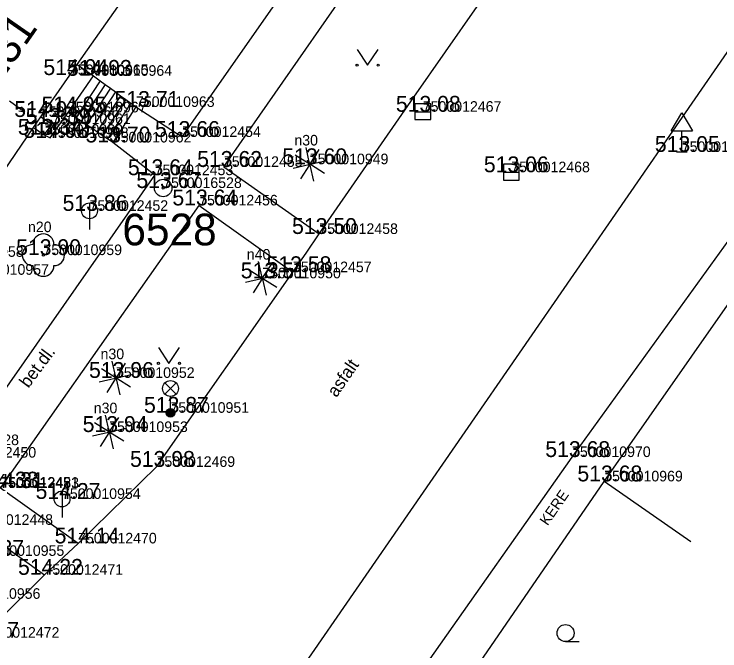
# Model space of a CAD drawing. Extents: x -669251 to -668549, y -1128351 to -1127698.
# Drawn here: x -668932.59 to -668899.21, y -1127946.27 to -1127916.15 of the extents above; entities that cross this region are included whole.
import ezdxf

# ---------------------------------------------------------------- set-up
doc = ezdxf.new("R2010")
doc.units = 0
for name, color, linetype in [('Vrstva 1', 7, 'Continuous'), ('Vrstva 10', 7, 'Continuous'), ('Vrstva 11', 7, 'Continuous'), ('Vrstva 2', 7, 'Continuous'), ('Vrstva 21', 7, 'Continuous'), ('Vrstva 22', 7, 'Continuous'), ('Vrstva 24', 7, 'Continuous'), ('Vrstva 27', 7, 'Continuous'), ('Vrstva 3', 7, 'Continuous'), ('Vrstva 33', 7, 'Continuous'), ('Vrstva 34', 7, 'Continuous'), ('Vrstva 36', 7, 'Continuous'), ('Vrstva 40', 7, 'Continuous'), ('Vrstva 43', 7, 'Continuous'), ('Vrstva 47', 7, 'Continuous'), ('Vrstva 5', 7, 'Continuous'), ('Vrstva 6', 7, 'Continuous'), ('Vrstva 63', 7, 'Continuous'), ('Vrstva 7', 7, 'Continuous')]:
    doc.layers.add(name, color=color, linetype=linetype)

msp = doc.modelspace()

# ---------------------------------------------------------------- linework, layer by layer
at = {"layer": 'Vrstva 1'}
for p, q in [((-668929.951, -1127919.033), (-668929.951, -1127919.033)), ((-668928.837, -1127919.068), (-668928.837, -1127919.068)), ((-668930.041, -1127920.798), (-668930.041, -1127920.798)), ((-668926.826, -1127920.54), (-668926.826, -1127920.54)), ((-668913.26, -1127920.768), (-668913.26, -1127920.768)), ((-668931.329, -1127921.015), (-668931.329, -1127921.015)), ((-668930.79, -1127921.349), (-668930.79, -1127921.349)), ((-668931.163, -1127921.858), (-668931.163, -1127921.858)), ((-668930.892, -1127922.005), (-668930.892, -1127922.005)), ((-668924.639, -1127921.96), (-668924.639, -1127921.96)), ((-668927.923, -1127922.22), (-668927.923, -1127922.22)), ((-668901.009, -1127922.669), (-668901.009, -1127922.669)), ((-668922.666, -1127923.376), (-668922.666, -1127923.376)), ((-668918.604, -1127923.25), (-668918.604, -1127923.25)), ((-668925.942, -1127923.768), (-668925.942, -1127923.768)), ((-668909.075, -1127923.63), (-668909.075, -1127923.63)), ((-668925.54, -1127924.375), (-668925.54, -1127924.375)), ((-668929.023, -1127925.456), (-668929.023, -1127925.456)), ((-668923.838, -1127925.199), (-668923.838, -1127925.199)), ((-668918.155, -1127926.549), (-668918.155, -1127926.549)), ((-668931.205, -1127927.548), (-668931.205, -1127927.548)), ((-668919.399, -1127928.356), (-668919.399, -1127928.356)), ((-668920.854, -1127928.647), (-668920.854, -1127928.647)), ((-668927.772, -1127933.358), (-668927.772, -1127933.358)), ((-668925.194, -1127935.007), (-668925.194, -1127935.007)), ((-668928.093, -1127935.917), (-668928.093, -1127935.917)), ((-668906.199, -1127937.1), (-668906.199, -1127937.1)), ((-668925.854, -1127937.566), (-668925.854, -1127937.566)), ((-668904.68, -1127938.252), (-668904.68, -1127938.252)), ((-668930.324, -1127939.081), (-668930.324, -1127939.081)), ((-668929.563, -1127941.186), (-668929.563, -1127941.186)), ((-668931.154, -1127942.671), (-668931.154, -1127942.671))]:
    msp.add_line(p, q, dxfattribs=at)
at = {"layer": 'Vrstva 10'}
for p, q in [((-668924.639, -1127921.96), (-668915.645, -1127909.032)), ((-668923.205, -1127953.195), (-668892.876, -1127909.291)), ((-668922.666, -1127923.376), (-668913.667, -1127910.439)), ((-668926.826, -1127920.54), (-668924.639, -1127921.96)), ((-668925.942, -1127923.768), (-668927.923, -1127922.22)), ((-668922.666, -1127923.376), (-668918.155, -1127926.549)), ((-668935.267, -1127937.128), (-668925.942, -1127923.768)), ((-668933.238, -1127938.566), (-668923.838, -1127925.199)), ((-668923.838, -1127925.199), (-668919.399, -1127928.356)), ((-668925.854, -1127937.566), (-668919.399, -1127928.356)), ((-668929.563, -1127941.186), (-668925.854, -1127937.566)), ((-668929.563, -1127941.186), (-668933.238, -1127938.566)), ((-668934.469, -1127940.308), (-668931.154, -1127942.671)), ((-668931.154, -1127942.671), (-668929.563, -1127941.186)), ((-668934.167, -1127945.646), (-668931.154, -1127942.671))]:
    msp.add_line(p, q, dxfattribs=at)
msp.add_lwpolyline([(-668919.399, -1127928.356), (-668918.777, -1127927.452), (-668918.155, -1127926.549), (-668913.684, -1127920.082), (-668909.196, -1127913.626), (-668908.554, -1127912.71), (-668907.91, -1127911.796), (-668905.751, -1127908.702), (-668903.61, -1127905.58), (-668903.236, -1127904.974), (-668902.699, -1127903.845), (-668902.381, -1127902.958), (-668902.019, -1127901.594), (-668901.763, -1127900.232), (-668901.68, -1127899.538), (-668901.657, -1127898.3), (-668901.741, -1127897.363), (-668901.861, -1127896.66), (-668902.133, -1127895.616), (-668902.513, -1127894.594), (-668903.003, -1127893.553), (-668903.409, -1127892.816), (-668904.098, -1127891.771)], dxfattribs=at)
at = {"layer": 'Vrstva 11'}
for p, q in [((-668929.604, -1127918.534), (-668928.837, -1127919.068)), ((-668930.041, -1127920.798), (-668928.837, -1127919.068)), ((-668928.837, -1127919.068), (-668928.523, -1127919.298)), ((-668928.523, -1127919.298), (-668929.667, -1127921.049)), ((-668928.281, -1127919.475), (-668929.417, -1127921.216)), ((-668928.523, -1127919.298), (-668928.281, -1127919.475)), ((-668928.281, -1127919.475), (-668928.038, -1127919.653)), ((-668928.038, -1127919.653), (-668929.168, -1127921.384)), ((-668927.796, -1127919.83), (-668928.919, -1127921.551)), ((-668928.038, -1127919.653), (-668927.796, -1127919.83)), ((-668927.796, -1127919.83), (-668927.553, -1127920.008)), ((-668927.553, -1127920.008), (-668928.67, -1127921.718)), ((-668927.553, -1127920.008), (-668927.311, -1127920.185)), ((-668927.311, -1127920.185), (-668928.421, -1127921.886)), ((-668927.068, -1127920.363), (-668928.172, -1127922.053)), ((-668927.311, -1127920.185), (-668927.068, -1127920.363)), ((-668927.068, -1127920.363), (-668926.826, -1127920.54)), ((-668930.892, -1127922.005), (-668930.041, -1127920.798)), ((-668929.667, -1127921.049), (-668930.041, -1127920.798)), ((-668926.826, -1127920.54), (-668927.923, -1127922.22)), ((-668929.417, -1127921.216), (-668929.667, -1127921.049)), ((-668931.669, -1127921.512), (-668931.163, -1127921.858)), ((-668929.168, -1127921.384), (-668929.417, -1127921.216)), ((-668928.919, -1127921.551), (-668929.168, -1127921.384)), ((-668928.67, -1127921.718), (-668928.919, -1127921.551)), ((-668928.421, -1127921.886), (-668928.67, -1127921.718)), ((-668931.163, -1127921.858), (-668930.892, -1127922.005)), ((-668928.172, -1127922.053), (-668928.421, -1127921.886)), ((-668927.923, -1127922.22), (-668928.172, -1127922.053))]:
    msp.add_line(p, q, dxfattribs=at)
at = {"layer": 'Vrstva 21'}
for p, q in [((-668906.199, -1127937.1), (-668895.924, -1127922.866)), ((-668915.923, -1127950.905), (-668906.199, -1127937.1))]:
    msp.add_line(p, q, dxfattribs=at)
at = {"layer": 'Vrstva 22'}
for p, q in [((-668918.612, -1127923.21), (-668918.784, -1127922.456)), ((-668918.638, -1127923.23), (-668919.294, -1127922.816)), ((-668918.17, -1127922.56), (-668918.584, -1127923.216)), ((-668918.564, -1127923.242), (-668917.81, -1127923.07)), ((-668919.398, -1127923.43), (-668918.644, -1127923.258)), ((-668918.624, -1127923.284), (-668919.038, -1127923.94)), ((-668918.596, -1127923.29), (-668918.424, -1127924.044)), ((-668917.914, -1127923.684), (-668918.57, -1127923.27)), ((-668920.862, -1127928.607), (-668921.034, -1127927.853)), ((-668920.42, -1127927.957), (-668920.834, -1127928.613)), ((-668920.888, -1127928.627), (-668921.544, -1127928.213)), ((-668920.814, -1127928.639), (-668920.06, -1127928.467)), ((-668921.648, -1127928.827), (-668920.894, -1127928.655)), ((-668920.874, -1127928.681), (-668921.288, -1127929.337)), ((-668920.846, -1127928.687), (-668920.674, -1127929.441)), ((-668920.164, -1127929.081), (-668920.82, -1127928.667)), ((-668927.78, -1127933.318), (-668927.952, -1127932.564)), ((-668927.338, -1127932.668), (-668927.752, -1127933.324)), ((-668927.806, -1127933.338), (-668928.462, -1127932.924)), ((-668927.732, -1127933.35), (-668926.978, -1127933.178)), ((-668928.566, -1127933.538), (-668927.812, -1127933.366)), ((-668927.792, -1127933.392), (-668928.206, -1127934.048)), ((-668927.764, -1127933.398), (-668927.592, -1127934.152)), ((-668927.082, -1127933.792), (-668927.738, -1127933.378)), ((-668928.101, -1127935.877), (-668928.273, -1127935.123)), ((-668928.127, -1127935.897), (-668928.783, -1127935.483)), ((-668927.659, -1127935.227), (-668928.073, -1127935.883)), ((-668928.053, -1127935.909), (-668927.299, -1127935.737)), ((-668928.887, -1127936.097), (-668928.133, -1127935.925)), ((-668928.113, -1127935.951), (-668928.527, -1127936.607)), ((-668928.085, -1127935.957), (-668927.913, -1127936.711)), ((-668927.403, -1127936.351), (-668928.059, -1127935.937))]:
    msp.add_line(p, q, dxfattribs=at)
for centre, radius in [((-668918.604, -1127923.25), 0.04), ((-668931.205, -1127927.548), 0.05), ((-668920.854, -1127928.647), 0.04), ((-668927.772, -1127933.358), 0.04), ((-668928.093, -1127935.917), 0.04)]:
    msp.add_circle(centre, radius, dxfattribs=at)
for centre, start, end in [((-668931.205, -1127927.048), 0, 180), ((-668931.705, -1127927.548), 90, 270), ((-668930.705, -1127927.548), 270, 90), ((-668931.205, -1127928.048), 180, 0)]:
    msp.add_arc(centre, 0.5, start, end, dxfattribs=at)
at = {"layer": 'Vrstva 24'}
for p, q in [((-668932.812, -1127920.259), (-668932.106, -1127920.776)), ((-668932.369, -1127920.72), (-668932.106, -1127920.776)), ((-668932.106, -1127920.776), (-668932.239, -1127920.543)), ((-668931.329, -1127921.015), (-668930.791, -1127921.35)), ((-668931.163, -1127921.858), (-668930.791, -1127921.35))]:
    msp.add_line(p, q, dxfattribs=at)
at = {"layer": 'Vrstva 27'}
for p, q in [((-668913.635, -1127920.768), (-668912.885, -1127920.768)), ((-668909.45, -1127923.63), (-668908.7, -1127923.63)), ((-668929.023, -1127925.081), (-668929.023, -1127926.331)), ((-668930.324, -1127938.706), (-668930.324, -1127939.956))]:
    msp.add_line(p, q, dxfattribs=at)
for points in [[(-668913.635, -1127921.142), (-668912.885, -1127921.142), (-668912.885, -1127920.392), (-668913.635, -1127920.392)], [(-668909.45, -1127924.004), (-668908.7, -1127924.004), (-668908.7, -1127923.254), (-668909.45, -1127923.254)]]:
    msp.add_lwpolyline(points, close=True, dxfattribs=at)
for centre in [(-668929.023, -1127925.456), (-668930.324, -1127939.081)]:
    msp.add_circle(centre, 0.375, dxfattribs=at)
at = {"layer": 'Vrstva 33'}
for p, q in [((-668925.459, -1127933.592), (-668924.929, -1127934.122)), ((-668925.459, -1127934.122), (-668924.929, -1127933.592)), ((-668925.194, -1127935.007), (-668925.194, -1127934.232))]:
    msp.add_line(p, q, dxfattribs=at)
for centre, radius in [((-668925.194, -1127933.857), 0.375), ((-668925.194, -1127935.007), 0.2), ((-668925.194, -1127935.007), 0.18), ((-668925.194, -1127935.007), 0.16), ((-668925.194, -1127935.007), 0.14), ((-668925.194, -1127935.007), 0.12), ((-668925.194, -1127935.007), 0.1), ((-668925.194, -1127935.007), 0.08), ((-668925.194, -1127935.007), 0.06), ((-668925.194, -1127935.007), 0.04), ((-668925.194, -1127935.007), 0.02)]:
    msp.add_circle(centre, radius, dxfattribs=at)
at = {"layer": 'Vrstva 34'}
for p, q in [((-668901.509, -1127921.669), (-668901.009, -1127920.819)), ((-668901.009, -1127920.819), (-668900.509, -1127921.669)), ((-668901.509, -1127921.669), (-668900.509, -1127921.669)), ((-668901.009, -1127922.669), (-668901.009, -1127921.669)), ((-668901.259, -1127922.669), (-668900.759, -1127922.669))]:
    msp.add_line(p, q, dxfattribs=at)
at = {"layer": 'Vrstva 36'}
for p, q in [((-668916.368, -1127917.816), (-668915.868, -1127918.566)), ((-668915.868, -1127918.566), (-668915.368, -1127917.816)), ((-668925.766, -1127931.919), (-668925.266, -1127932.669)), ((-668925.266, -1127932.669), (-668924.766, -1127931.919)), ((-668906.506, -1127945.829), (-668905.856, -1127945.826))]:
    msp.add_line(p, q, dxfattribs=at)
for centre, radius in [((-668916.368, -1127918.566), 0.05), ((-668915.368, -1127918.566), 0.05), ((-668925.766, -1127932.669), 0.05), ((-668924.766, -1127932.669), 0.05), ((-668906.507, -1127945.426), 0.403)]:
    msp.add_circle(centre, radius, dxfattribs=at)
at = {"layer": 'Vrstva 5'}
for p, q in [((-668929.604, -1127918.534), (-668921.408, -1127906.757)), ((-668929.951, -1127919.033), (-668929.604, -1127918.534)), ((-668931.669, -1127921.512), (-668931.329, -1127921.015)), ((-668935.858, -1127927.631), (-668931.669, -1127921.512))]:
    msp.add_line(p, q, dxfattribs=at)
at = {"layer": 'Vrstva 6'}
msp.add_line((-668931.329, -1127921.015), (-668929.951, -1127919.033), dxfattribs=at)
at = {"layer": 'Vrstva 63'}
for radius in [0.412, 0.412, 0.05, 0.05]:
    msp.add_circle((-668925.54, -1127924.375), radius, dxfattribs=at)
at = {"layer": 'Vrstva 7'}
for p, q in [((-668904.68, -1127938.252), (-668894.6, -1127923.822)), ((-668914.126, -1127952.001), (-668904.68, -1127938.252)), ((-668900.581, -1127941.115), (-668904.68, -1127938.252))]:
    msp.add_line(p, q, dxfattribs=at)

# ---------------------------------------------------------------- texts
at = {"layer": 'Vrstva 2'}
for s, p in [('7500010965', (-668929.951, -1127919.033)), ('7500010964', (-668928.837, -1127919.068)), ('7500010963', (-668926.826, -1127920.54)), ('7500010966', (-668931.329, -1127921.015)), ('7500010967', (-668930.041, -1127920.798)), ('7500012467', (-668913.26, -1127920.768)), ('7500010961', (-668930.79, -1127921.349)), ('7500010960', (-668931.163, -1127921.858)), ('7500010968', (-668930.892, -1127922.005)), ('7500012454', (-668924.639, -1127921.96)), ('7500010962', (-668927.923, -1127922.22)), ('7500011025', (-668901.009, -1127922.669)), ('7500010949', (-668918.604, -1127923.25)), ('7500012455', (-668922.666, -1127923.376)), ('7500012468', (-668909.075, -1127923.63)), ('7500012453', (-668925.942, -1127923.768)), ('7500016528', (-668925.54, -1127924.375)), ('7500012456', (-668923.838, -1127925.199)), ('7500012452', (-668929.023, -1127925.456)), ('7500012458', (-668918.155, -1127926.549)), ('7500010958', (-668935.858, -1127927.631)), ('7500010959', (-668931.205, -1127927.548)), ('7500012457', (-668919.399, -1127928.356)), ('7500010957', (-668934.661, -1127928.478)), ('7500010950', (-668920.854, -1127928.647)), ('7500010952', (-668927.772, -1127933.358)), ('7500010951', (-668925.194, -1127935.007)), ('7500010953', (-668928.093, -1127935.917)), ('7500010928', (-668936.079, -1127936.537)), ('7500012450', (-668935.267, -1127937.128)), ('7500010970', (-668906.199, -1127937.1)), ('7500012469', (-668925.854, -1127937.566)), ('7500010969', (-668904.68, -1127938.252)), ('7500012451', (-668933.251, -1127938.544)), ('7500012483', (-668933.238, -1127938.566)), ('7500010954', (-668930.324, -1127939.081)), ('7500012448', (-668934.469, -1127940.308)), ('7500012470', (-668929.563, -1127941.186)), ('7500010955', (-668933.936, -1127941.775)), ('7500012471', (-668931.154, -1127942.671)), ('7500010956', (-668935.065, -1127943.807)), ('7500012472', (-668934.167, -1127945.646))]:
    msp.add_text(s, height=0.5, dxfattribs=at).set_placement(p)
at = {"layer": 'Vrstva 3'}
for s, p in [('514.94 ', (-668931.205, -1127919.033)), ('514.93 ', (-668930.091, -1127919.068)), ('513.71 ', (-668927.841, -1127920.54)), ('514.95 ', (-668931.295, -1127920.798)), ('513.08 ', (-668914.534, -1127920.768)), ('514.94 ', (-668932.583, -1127921.015)), ('513.39 ', (-668932.045, -1127921.349)), ('513.34 ', (-668932.415, -1127921.858)), ('514.93 ', (-668932.146, -1127922.005)), ('513.70 ', (-668929.211, -1127922.22)), ('513.66 ', (-668925.927, -1127921.96)), ('513.05 ', (-668902.283, -1127922.669)), ('513.60 ', (-668919.905, -1127923.25)), ('513.62 ', (-668923.932, -1127923.376)), ('513.64 ', (-668927.208, -1127923.768)), ('513.06 ', (-668910.371, -1127923.63)), ('513.67 ', (-668926.806, -1127924.375)), ('513.64 ', (-668925.104, -1127925.199)), ('513.86 ', (-668930.297, -1127925.456)), ('513.50 ', (-668919.443, -1127926.549)), ('513.90 ', (-668932.495, -1127927.548)), ('513.58 ', (-668920.651, -1127928.356)), ('513.51 ', (-668921.869, -1127928.647)), ('513.96 ', (-668929.048, -1127933.358)), ('513.87 ', (-668926.446, -1127935.007)), ('513.94 ', (-668929.347, -1127935.917)), ('513.68 ', (-668907.465, -1127937.1)), ('513.98 ', (-668927.108, -1127937.566)), ('513.68 ', (-668905.946, -1127938.252)), ('514.33 ', (-668934.503, -1127938.544)), ('514.31 ', (-668934.253, -1127938.566)), ('514.27 ', (-668931.576, -1127939.081)), ('514.14 ', (-668930.673, -1127941.186)), ('514.37 ', (-668935.188, -1127941.775)), ('514.22 ', (-668932.406, -1127942.671)), ('514.37 ', (-668935.419, -1127945.646))]:
    msp.add_text(s, height=0.75, dxfattribs=at).set_placement(p)
at = {"layer": 'Vrstva 40'}
for s, rotation, p in [('bet.dl.', 53.2593, (-668931.914, -1127933.872)), ('asfalt', 55.4077, (-668917.343, -1127934.315))]:
    msp.add_text(s, height=0.6, rotation=rotation, dxfattribs=at).set_placement(p)
at = {"layer": 'Vrstva 43'}
msp.add_text('4231', height=1.5, rotation=55.1908, dxfattribs=at).set_placement((-668933.988, -1127920.459))
at = {"layer": 'Vrstva 47'}
for s, height, p in [('n30', 0.5, (-668919.334, -1127922.364)), ('n20', 0.499, (-668931.934, -1127926.462)), ('n40', 0.5, (-668921.584, -1127927.761)), ('n30', 0.5, (-668928.502, -1127932.472)), ('n30', 0.5, (-668928.823, -1127935.031))]:
    msp.add_text(s, height=height, dxfattribs=at).set_placement(p)
msp.add_text('KERE', height=0.5, rotation=55.5101, dxfattribs=at).set_placement((-668907.355, -1127940.38))
at = {"layer": 'Vrstva 63'}
msp.add_text('6528', height=1.5, dxfattribs=at).set_placement((-668927.471, -1127927.087))
msp.add_text('6528', height=1.5, dxfattribs=at).set_placement((-668927.471, -1127927.087))

doc.saveas('drawing.dxf')
